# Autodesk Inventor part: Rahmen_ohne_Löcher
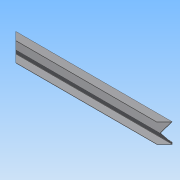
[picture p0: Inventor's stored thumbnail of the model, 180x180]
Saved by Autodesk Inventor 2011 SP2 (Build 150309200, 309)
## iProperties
Created: 2009-11
Part Number: Rahmen_ohne_Löcher
Document SubType Name: Modeling
Designer: gkramp
Density: 1 g/cm^3
Author: gkramp
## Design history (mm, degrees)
derived "Masterbaugruppe.iam"
sketch "Skizze1_1"
  geometry: L1 (-40, 100)-(0, 100) reference; L2 (0, 100)-(-30, 50) reference; L3 (-30, 50)-(-3.477, 10) reference; L4 (-3.477, 10)-(0, 10) reference; L5 (0, 10)-(0, 0) reference; L6 (0, 0)-(-40, 0) reference; L7 (0, 37.459)-(0, -9.286) reference; L8 (-3.707, 0)-(22.509, 0) reference; L9 (-40, 98.5)-(-2.649, 98.5) reference; L10 (-2.649, 98.5)-(-31.773, 49.96) reference; L11 (-31.773, 49.96)-(-4.283, 8.5) reference; L12 (-4.283, 8.5)-(-1.5, 8.5) reference; L13 (-1.5, 8.5)-(-1.5, 1.5) reference; L14 (-1.5, 1.5)-(-40, 1.5) reference; L15 (-40, 100)-(-40, 30.181); L16 (-40, 1.5)-(-40, 0); L17 (-40, 100)-(-40, 98.5) reference; L18 (-40, 1.5)-(-40, 0) reference
  constraints: 4 end point
extrude "Extrusion1" new body sketch "Skizze1_1" stored distance "d11" = 10; taper "d16" = 0 deg
node "Volumenkörper1"
node "Volumenkörpern"
node "Oberflächenkörpern"
node "BaugruppenMasterskizze.ipt:1"
node "Profilskizze.ipt:1"
node "Profilskizze.ipt:2"
sketch "Skizze1"
  geometry: L1 (-450, 500)-(-305.18, 355.18) reference; L2 (450, 500)-(305.18, 355.18) reference; L3 (-450, -500)-(-305.18, -355.18) reference; L4 (-305.18, -355.18)-(305.18, -355.18) reference; L5 (305.18, -355.18)-(450, -500) reference; L6 (305.18, 355.18)-(305.18, -355.18) reference; L7 (305.18, 355.18)-(-305.18, 355.18) reference; L8 (-305.18, 355.18)-(-305.18, -355.18) reference; L9 (-450, -500)-(450, -500) reference; L10 (450, -500)-(450, 500) reference; L11 (450, 500)-(-450, 500) reference; L12 (-450, 500)-(-450, -500) reference; L13 (0, 23.685)-(0, -25.883) reference; L14 (-18.992, 0)-(22.934, 0) reference; 9 further points
  constraints: 1 other
workplane "Arbeitsebene1"
workplane "Arbeitsebene2"
workplane "Arbeitsebene3"
workplane "Arbeitsebene4"
sketch "Skizze1_2"
  geometry: L1 (-40, 100)-(0, 100) reference; L2 (0, 100)-(-30, 50) reference; L3 (-30, 50)-(-3.477, 10) reference; L4 (-3.477, 10)-(0, 10) reference; L5 (0, 10)-(0, 0) reference; L6 (0, 0)-(-40, 0) reference; L7 (0, 37.459)-(0, -9.286) reference; L8 (-3.707, 0)-(22.509, 0) reference; L9 (-40, 98.5)-(-2.649, 98.5) reference; L10 (-2.649, 98.5)-(-31.773, 49.96) reference; L11 (-31.773, 49.96)-(-4.283, 8.5) reference; L12 (-4.283, 8.5)-(-1.5, 8.5) reference; L13 (-1.5, 8.5)-(-1.5, 1.5) reference; L14 (-1.5, 1.5)-(-40, 1.5) reference; L15 (-40, 100)-(-40, 98.5) reference; L16 (-40, 1.5)-(-40, 0) reference
other parameters: "d2" = 0, "d4" = 0, "d6" = 0, "d8" = 0, "d12" = 0, "d10" = 144.82031, "d12_1" = 90 deg, "d13" = 90 deg, "d14" = 90 deg, "d15" = 90 deg, "d4_2" = 3.4774, "d7_1" = 1.5, "d4_3" = 3.4774, "d7_2" = 1.5
